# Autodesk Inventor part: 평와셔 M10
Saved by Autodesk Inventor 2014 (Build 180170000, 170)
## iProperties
Created: 2026-06
Part Number: 평와셔 M10
Material: 강철, 연강
Document SubType Name: Modeling
Designer: dg
Density: 7.86 g/cm^3
Appearance: 강철
Mass: 3.95087 g
Surface Area: 7.03717 cm^2
Volume: 0.502655 cm^3
Author: jhkim
Description: 평면 와셔
Creation Date: 2026-05-29
Sending System: Autodesk Inventor 2027
Preprocessor: ST-DEVELOPER v20.1
Author: dg
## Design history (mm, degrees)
node "평와셔 M101"
body "Solid1"
node "기준1"
